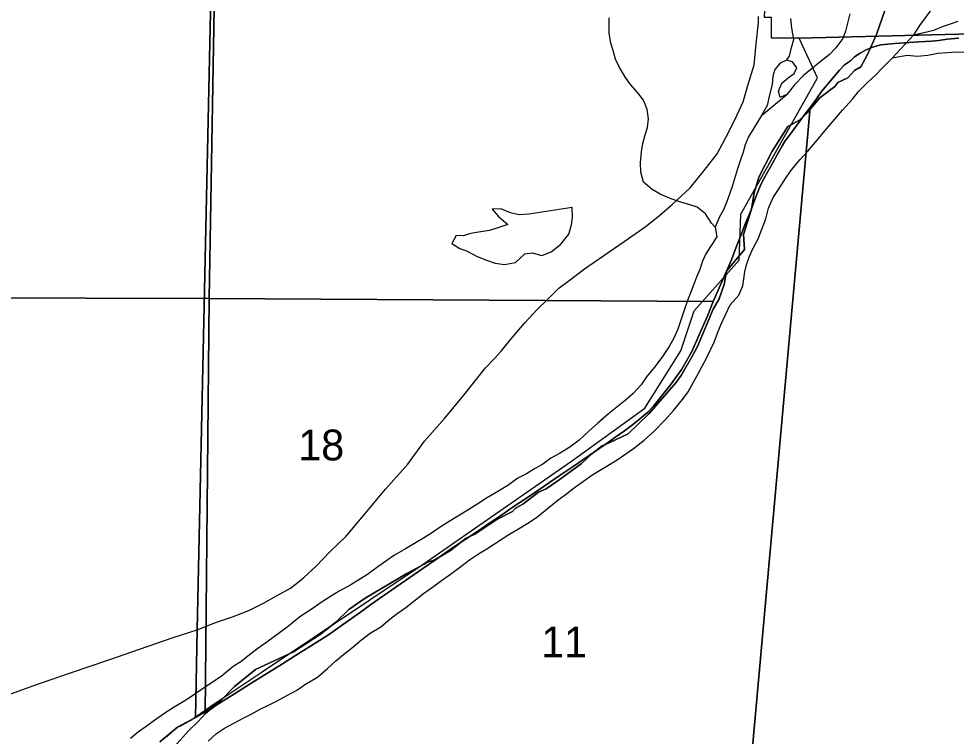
# Model space of a CAD drawing. Extents: x 1310247 to 1552180, y 377264 to 706493.
# Drawn here: x 1376326 to 1383052, y 499946 to 505092 of the extents above; entities that cross this region are included whole.
import ezdxf

# ---------------------------------------------------------------- set-up
doc = ezdxf.new("R2010")
doc.units = 0
for name, color, linetype in [('GM_X_Corporation', 7, 'Continuous'), ('GM_X_Major_River', 7, 'Continuous'), ('GM_X_Minor_Lake', 7, 'Continuous'), ('GM_X_Minor_River', 7, 'Continuous'), ('GM_X_Section', 7, 'Continuous'), ('GM_X_Section_Text', 7, 'Continuous'), ('GM_X_State_Route', 7, 'Continuous'), ('GM_X_Township', 7, 'Continuous')]:
    doc.layers.add(name, color=color, linetype=linetype)

msp = doc.modelspace()

# ---------------------------------------------------------------- linework, layer by layer
at = {"layer": 'GM_X_Corporation'}
for points in [[(1383353.6, 504989.2), (1381925.6, 504951.4), (1381725.6, 504951.4), (1381725.6, 505100.1), (1381677.1, 505100.2), (1381698.4, 505559.8), (1381687.8, 506000.9), (1381661.3, 506197.5), (1381703.8, 506404.7), (1381746.4, 506856.4), (1381788.9, 507223), (1383271.5, 507225.7)], [(1377389.1, 499942.2), (1377435.9, 499986.6), (1377464.5, 500010.5), (1377489.6, 500021.6), (1377522.2, 500040.5), (1377561.1, 500061.7), (1377728.2, 500177.6), (1378073.2, 500407.8), (1379228.1, 501181.2), (1380292.8, 501917.7), (1380817.6, 502298.2), (1381075.9, 502710.6), (1381171.9, 502996.2), (1381495.1, 503360.3), (1381505.7, 503689.7), (1382056.7, 504667), (1381925.6, 504951.4), (1383353.6, 504989.2)]]:
    msp.add_lwpolyline(points, dxfattribs=at)
at = {"layer": 'GM_X_Major_River'}
for p, q in [((1382591.4, 504808.4), (1382748.5, 504977)), ((1381654.9, 504397.6), (1381835.6, 504547.5))]:
    msp.add_line(p, q, dxfattribs=at)
for points in [[(1382748.5, 504977), (1382790.5, 505042.2), (1382838.4, 505107.2), (1382884.3, 505170.2), (1382917.9, 505223.6), (1382949.5, 505279), (1382985.2, 505336.3), (1383025.3, 505407.6), (1383069.4, 505480.7)], [(1382289.1, 505128), (1382257.5, 505002.2), (1382238.1, 504950.5), (1382188, 504883.6), (1382140.5, 504832.6), (1382072.8, 504780.2), (1382009.2, 504727.6), (1381955.8, 504684.9), (1381891.8, 504618.3), (1381835.6, 504547.5)], [(1377684.2, 499911.5), (1377745.9, 499966.1), (1377803.2, 500004.7), (1377868.4, 500039.1), (1377941.7, 500077.3), (1377998.6, 500105.9), (1378053.7, 500138.6), (1378122.8, 500170.9), (1378179.8, 500199.5), (1378253.2, 500241.7), (1378326.5, 500277.9), (1378379.7, 500316.7), (1378469.5, 500370.5), (1378541.4, 500430.8), (1378601.2, 500487.5), (1378666.9, 500542), (1378722.2, 500584.7), (1378775.6, 500629.5), (1378847.4, 500685.8), (1378922.9, 500730), (1378988.7, 500786.5), (1379042, 500827.2), (1379103.4, 500869.8), (1379160.8, 500914.5), (1379230.6, 500970.8), (1379294, 501015.3), (1379349.3, 501056), (1379423, 501108.3), (1379496.7, 501162.6), (1379560.3, 501211.1), (1379623.7, 501253.6), (1379684.9, 501290.1), (1379740.1, 501326.8), (1379842.2, 501392.4), (1379911.6, 501432.7), (1379978.9, 501473.1), (1380040.3, 501515.6), (1380118.2, 501577.8), (1380194.2, 501638), (1380245.4, 501676.8), (1380313.1, 501729.3), (1380376.6, 501775.8), (1380429.8, 501814.5), (1380480.8, 501845.3), (1380540, 501879.9), (1380619.6, 501928), (1380674.8, 501966.7), (1380736.2, 502009.2), (1380814.1, 502069.4), (1380884.1, 502133.8), (1380962.6, 502216.1), (1381022.7, 502282.8), (1381087, 502361.4), (1381128.7, 502416.6), (1381168.9, 502489.8), (1381202.6, 502549.2), (1381230.1, 502600.7), (1381259.8, 502658.2), (1381289.5, 502717.6), (1381315.1, 502771.2), (1381339, 502836.9), (1381362.7, 502896.5), (1381394.6, 502964), (1381428.8, 503039.4), (1381491, 503110.1), (1381520.9, 503175.6), (1381535.7, 503275.6), (1381547.1, 503327.6), (1381568.9, 503389.2), (1381594.6, 503446.8), (1381630.5, 503514.2), (1381667.2, 503605.6), (1381684.7, 503657.4), (1381704.8, 503733.2), (1381739.1, 503810.6), (1381780.9, 503873.8), (1381827.1, 503946.9), (1381870.9, 504008), (1381933.2, 504082.7), (1381987, 504141.5), (1382053.4, 504220.1), (1382109.5, 504288.9), (1382167.5, 504355.7), (1382235.9, 504436.2), (1382308.3, 504514.6), (1382350, 504569.8), (1382416, 504634.3), (1382471.6, 504687.1), (1382521.2, 504738), (1382591.4, 504808.4)], [(1381835.6, 504547.5), (1381788.9, 504526.6), (1381776.1, 504571.2), (1381799.7, 504628.8), (1381849, 504669.7), (1381887.9, 504698.8), (1381909.2, 504740.4), (1381878.2, 504783.4), (1381834.4, 504794.6), (1381789.7, 504773.7), (1381750.2, 504726.6), (1381736.9, 504680.7)], [(1381736.9, 504680.7), (1381731.3, 504620.6), (1381713.2, 504546.7), (1381695, 504468.9), (1381654.9, 504397.6)], [(1381654.9, 504397.6), (1381560.4, 504245.4), (1381536.7, 504187.8), (1381523.2, 504133.9), (1381501.4, 504072.2), (1381481.8, 504014.5), (1381446.4, 503894.9), (1381426.8, 503841.2), (1381402.9, 503773.5), (1381381.4, 503721.8), (1381353.9, 503670.3), (1381321.8, 503596.8), (1381333.9, 503528.2), (1381289.9, 503459.1), (1381254.3, 503405.8), (1381230.8, 503354.2), (1381211.1, 503294.4), (1381189.5, 503238.7), (1381167.8, 503181.1), (1381144.2, 503125.4), (1381120.4, 503063.8), (1381096.4, 502994.1), (1381078.8, 502936.3), (1381054.8, 502864.6), (1381026.9, 502801.1), (1380991.2, 502741.8), (1380938.8, 502662.8), (1380886.7, 502593.9), (1380830.6, 502523.1), (1380790.9, 502465.9), (1380735.1, 502405.1), (1380677.5, 502354.4), (1380615.9, 502305.8), (1380556.4, 502259.2), (1380480.3, 502190.9), (1380418.6, 502136.3), (1380346.5, 502070), (1380278.9, 502019.5), (1380205.4, 501973.3), (1380142.3, 501940.8), (1380084.9, 501896.2), (1380025.8, 501863.6), (1379968.6, 501829), (1379907.5, 501796.5), (1379835.9, 501744.2), (1379739.9, 501686.5), (1379680.8, 501653.9), (1379619.5, 501613.4), (1379556.2, 501572.9), (1379501.1, 501538.2), (1379413.3, 501486.3), (1379356.1, 501449.7), (1379300.9, 501413), (1379229.4, 501366.7), (1379176.4, 501336), (1379100.9, 501289.8), (1379021.3, 501243.7), (1378966.1, 501207), (1378902.7, 501160.5), (1378828.9, 501106.2), (1378777.9, 501075.5), (1378708.4, 501031.1), (1378625, 500987.2), (1378561.7, 500948.7), (1378510.6, 500915.9), (1378424.7, 500856), (1378342.9, 500801.9), (1378260.8, 500735.8), (1378187, 500679.5), (1378115.3, 500627.2), (1378041.7, 500574.9), (1377982.2, 500530.3), (1377920.6, 500479.8), (1377865.5, 500445.1), (1377779.3, 500375.1), (1377701.6, 500324.9), (1377628, 500274.7), (1377566.6, 500232.1), (1377505.4, 500193.6), (1377440.1, 500155.2), (1377374.7, 500112.7), (1377303, 500060.4), (1377239.6, 500015.9), (1377186.3, 499977.1), (1377126.9, 499930.5)]]:
    msp.add_lwpolyline(points, dxfattribs=at)
at = {"layer": 'GM_X_Minor_Lake'}
for points in [[(1379985.8, 503689.1), (1379917.4, 503684.9), (1379853.6, 503698.7), (1379784.2, 503728.7), (1379721.9, 503726.4), (1379768.6, 503672.9), (1379835.3, 503616.8), (1379770.4, 503594.5), (1379703.7, 503574.2), (1379625, 503560.2), (1379570.6, 503551.6), (1379513.9, 503535.1), (1379463.8, 503536.4), (1379432.2, 503481), (1379491.3, 503443.3), (1379543, 503423.8), (1379610.3, 503389.8), (1379673.7, 503362), (1379743.4, 503340), (1379811.3, 503330.1), (1379890, 503344.1), (1379957.9, 503404.6), (1380008.3, 503413.2), (1380078, 503393.3), (1380144.9, 503419.6), (1380214.7, 503476), (1380272.8, 503546.8), (1380290.8, 503614.6), (1380298.3, 503668.6), (1380296.2, 503739)], [(1380296.2, 503739), (1379985.8, 503689.1)]]:
    msp.add_lwpolyline(points, dxfattribs=at)
at = {"layer": 'GM_X_Minor_River'}
msp.add_line((1382748.5, 504977), (1382591.4, 504808.4), dxfattribs=at)
for points in [[(1381321.8, 503596.8), (1381296.5, 503625.7), (1381252.2, 503693.1), (1381193.3, 503741), (1381125.7, 503762.9), (1381065.9, 503778.5), (1380994.4, 503804.6), (1380928.9, 503832.5), (1380869.6, 503866.2), (1380808.9, 503920.1), (1380788.8, 503991), (1380786.6, 504059.3), (1380792.8, 504137.5), (1380802.5, 504197.5), (1380820.3, 504259.4), (1380837.7, 504311.1), (1380843.5, 504373.3), (1380833.3, 504441.8), (1380807.1, 504508.9), (1380768.3, 504560.1), (1380713.8, 504619.9), (1380679.1, 504671), (1380634.9, 504742.6), (1380608.4, 504801.5), (1380590.1, 504864.3), (1380573.5, 504917), (1380561.4, 504987.7), (1380560.8, 505039.9), (1380562.4, 505098.1)], [(1381834.4, 504794.6), (1381855.3, 504824.2), (1381871, 504886.1), (1381886.7, 504943.9), (1381872.8, 505024.7), (1381864.7, 505093.2)], [(1382748.5, 504977), (1382891.9, 505009.3), (1382960.9, 505037.6), (1383011.6, 505056.3), (1383066.3, 505074.9)], [(1383108.3, 504850.8), (1383046.1, 504852.4), (1382989.8, 504847.9), (1382919.4, 504841.8), (1382846.8, 504827.7), (1382770.3, 504821.7), (1382700.3, 504827.6), (1382591.4, 504808.4)]]:
    msp.add_lwpolyline(points, dxfattribs=at)
at = {"layer": 'GM_X_Section'}
for points in [[(1372445.8, 508439.6), (1377782.5, 508365.7), (1377691.2, 503085.5), (1372373.2, 503099.2)], [(1377691.2, 503085.5), (1381309, 503064.7), (1381268.7, 502965.6), (1381154.8, 502706.2), (1381083.8, 502577.8), (1381001.2, 502465.7), (1380879.8, 502314.4), (1380838.8, 502271.4), (1380795.9, 502234.4), (1380763.2, 502205.1), (1380718.5, 502172.1), (1380671.6, 502135.2), (1380610.7, 502092.6), (1380539.5, 502042.2), (1380456.2, 501986.1), (1380303.8, 501881.6), (1380204.3, 501813.9), (1380094.6, 501740.4), (1379976.7, 501659.1), (1379867.1, 501587.6), (1379781.7, 501527.5), (1379698.4, 501471.4), (1379619.1, 501417.2), (1379527.8, 501357.3), (1379438.4, 501297.3), (1379316.5, 501212.1), (1379225, 501148.2), (1378968.9, 500972.1), (1378859.2, 500894.6), (1378777.8, 500836.4), (1378647.7, 500745.4), (1378548.1, 500673.7), (1378446.5, 500608), (1378312.7, 500525.1), (1378217.3, 500465.2), (1378117.8, 500403.5), (1377986, 500322.5), (1377874.3, 500249.1), (1377793.2, 500200.9), (1377740.4, 500166.1), (1377697.7, 500135.1), (1377663, 500105.9)]]:
    msp.add_lwpolyline(points, close=True, dxfattribs=at)
for points in [[(1383070.3, 504952.5), (1382986.1, 504944.4), (1382927.9, 504935.7), (1382873.8, 504931), (1382829.7, 504928), (1382783.7, 504925), (1382611.4, 504913), (1382511.2, 504905.3), (1382450.8, 504888.7), (1382404.3, 504867.7), (1382361.8, 504844.7), (1382321.2, 504819.6), (1382292.6, 504790.3), (1382249.9, 504761.2), (1382215, 504722), (1382085.5, 504569), (1382048.3, 504517.8), (1382002.8, 504454.9), (1381959.6, 504399.9), (1381858.4, 504260.2), (1381823.4, 504217), (1381800.4, 504175.5), (1381769.2, 504120.2), (1381740, 504068.9), (1381698.2, 503991.8), (1381671.1, 503944.4), (1381652.3, 503906.9), (1381633.3, 503863.3), (1381605.7, 503795.9), (1381580.1, 503722.5), (1381535.5, 503613.5), (1381510, 503548.1), (1381473.9, 503452.9), (1381439.8, 503361.7), (1381404, 503282.5), (1381309, 503064.7), (1377691.2, 503085.5), (1377782.5, 508365.7)], [(1381559.9, 499522.7), (1382002.8, 504454.9), (1382048.3, 504517.8), (1382085.5, 504569), (1382215, 504722), (1382249.9, 504761.2), (1382292.6, 504790.3), (1382321.2, 504819.6), (1382361.8, 504844.7), (1382404.3, 504867.7), (1382450.8, 504888.7), (1382511.2, 504905.3), (1382611.4, 504913), (1382783.7, 504925), (1382829.7, 504928), (1382873.8, 504931), (1382927.9, 504935.7), (1382986.1, 504944.4), (1383070.3, 504952.5)], [(1377441.6, 499870.9), (1377544.2, 499984.6), (1377613.8, 500053), (1377663, 500105.9), (1377697.7, 500135.1), (1377740.4, 500166.1), (1377793.2, 500200.9), (1377874.3, 500249.1), (1377986, 500322.5), (1378117.8, 500403.5), (1378217.3, 500465.2), (1378312.7, 500525.1), (1378446.5, 500608), (1378548.1, 500673.7), (1378647.7, 500745.4), (1378777.8, 500836.4), (1378859.2, 500894.6), (1378968.9, 500972.1), (1379225, 501148.2), (1379316.5, 501212.1), (1379438.4, 501297.3), (1379527.8, 501357.3), (1379619.1, 501417.2), (1379698.4, 501471.4), (1379781.7, 501527.5), (1379867.1, 501587.6), (1379976.7, 501659.1), (1380094.6, 501740.4), (1380204.3, 501813.9), (1380303.8, 501881.6), (1380456.2, 501986.1), (1380539.5, 502042.2), (1380610.7, 502092.6), (1380671.6, 502135.2), (1380718.5, 502172.1), (1380763.2, 502205.1), (1380795.9, 502234.4), (1380838.8, 502271.4), (1380879.8, 502314.4), (1381001.2, 502465.7), (1381083.8, 502577.8), (1381154.8, 502706.2), (1381268.7, 502965.6), (1381309, 503064.7), (1381404, 503282.5), (1381439.8, 503361.7), (1381473.9, 503452.9), (1381510, 503548.1), (1381535.5, 503613.5), (1381580.1, 503722.5), (1381605.7, 503795.9), (1381633.3, 503863.3), (1381652.3, 503906.9), (1381671.1, 503944.4), (1381698.2, 503991.8), (1381740, 504068.9), (1381769.2, 504120.2), (1381800.4, 504175.5), (1381823.4, 504217), (1381858.4, 504260.2), (1381959.6, 504399.9), (1382002.8, 504454.9), (1381559.9, 499522.7)], [(1372373.3, 499782.9), (1372373.2, 503099.2), (1377691.2, 503085.5), (1377663, 500105.9), (1377613.8, 500053), (1377544.2, 499984.6), (1377441.6, 499870.9)]]:
    msp.add_lwpolyline(points, dxfattribs=at)
at = {"layer": 'GM_X_State_Route'}
for points in [[(1379743.3, 502660.6), (1379786.5, 502707.5), (1379871.5, 502810.1), (1379956.4, 502910.4), (1380043.7, 503003.6), (1380123.9, 503083.8), (1380199.7, 503159.8), (1380274.8, 503214.7), (1380385.8, 503298.5), (1380523.7, 503394), (1380670, 503493.1), (1380821, 503600.4), (1380923.6, 503681.8), (1381015.6, 503762), (1381143, 503880), (1381244.4, 504002.6), (1381335.6, 504123.3), (1381397.7, 504240.6), (1381466.2, 504371.8), (1381523, 504497), (1381557.7, 504613.2), (1381601, 504762.3), (1381616.7, 504911.4), (1381634, 505064), (1381634.3, 505108.4)], [(1376242.1, 500240), (1376435.6, 500309.6), (1376690.3, 500398), (1376980.5, 500497.1), (1377191.6, 500570.3), (1377433.4, 500654), (1377605.7, 500708.3), (1377744.8, 500764.9), (1377860.4, 500802.6), (1377977.2, 500848.6), (1378082.2, 500899.3), (1378175.3, 500952.4), (1378276.7, 501008.3), (1378343.1, 501061.6), (1378372.2, 501084.9), (1378459.6, 501165.7), (1378557.5, 501268.3), (1378674.3, 501381.8), (1378802.9, 501531.5), (1378957.3, 501717.9), (1379117.2, 501897.6), (1379236.9, 502062.3), (1379381.2, 502225), (1379520, 502391.4), (1379675.7, 502587.2), (1379743.3, 502660.6)]]:
    msp.add_lwpolyline(points, dxfattribs=at)
at = {"layer": 'GM_X_Township'}
for points in [[(1364164.5, 513845.1), (1368014.4, 513825.3), (1368609.6, 513814.9), (1369066.7, 513817.2), (1369488, 513814.9), (1370392.5, 513802.6), (1371848.8, 513777.9), (1372591.9, 513770.6), (1373324, 513763.4), (1375822.3, 513738.9), (1377854.8, 513715.5), (1377805.2, 510595.3), (1377766.1, 508131), (1377605.8, 500708.3), (1377593.7, 500080.7), (1377464.5, 500010.5), (1377338.3, 499907)], [(1382560.9, 505212.7), (1382478.6, 504979), (1382415.9, 504835.6), (1382366.6, 504747.6), (1382322.9, 504720.1), (1382274.1, 504669.1), (1382203.1, 504634.1), (1382181.1, 504605.8), (1382073.1, 504525.2), (1381982.1, 504417.3), (1381926.8, 504364.7), (1381842.7, 504318.6), (1381729, 504137.6), (1381635, 503956), (1381601.4, 503844), (1381582.9, 503726.6), (1381524.4, 503545.6), (1381532.5, 503435.7), (1381403.8, 503282.6), (1381387.8, 503186.1), (1381350.5, 503083.2), (1381307.8, 503008.3), (1381195.4, 502740.9), (1381152.4, 502663), (1381079, 502533.4), (1381040.2, 502479.9), (1380847.6, 502258.1), (1380698.2, 502114.4), (1380567.8, 502053.7), (1380512.6, 502028.1), (1380436.8, 501972.4), (1380360.6, 501900.4), (1380186.3, 501772.1), (1380108.9, 501719.3), (1380055.9, 501695.6), (1379943.1, 501611.4), (1379890.1, 501582.3), (1379867.3, 501559), (1379756.3, 501499.4), (1379597.4, 501395.3), (1379535.7, 501365.6), (1379423.5, 501279.3), (1379306.5, 501209.9), (1379265.8, 501195.8), (1379110.6, 501114.1), (1378811.5, 500935.3), (1378695.1, 500855), (1378600.7, 500763.9), (1378488, 500676.2), (1378297, 500551.1), (1378025.2, 500424.8), (1377873.6, 500302.2), (1377773.2, 500200.4), (1377700.3, 500142.9), (1377593.7, 500080.7), (1377605.8, 500708.3), (1377766.1, 508131)], [(1377338.3, 499907), (1377464.5, 500010.5), (1377593.7, 500080.7), (1377700.3, 500142.9), (1377773.2, 500200.4), (1377873.6, 500302.2), (1378025.2, 500424.8), (1378297, 500551.1), (1378488, 500676.2), (1378600.7, 500763.9), (1378695.1, 500855), (1378811.5, 500935.3), (1379110.6, 501114.1), (1379265.8, 501195.8), (1379306.5, 501209.9), (1379423.5, 501279.3), (1379535.7, 501365.6), (1379597.4, 501395.3), (1379756.3, 501499.4), (1379867.3, 501559), (1379890.1, 501582.3), (1379943.1, 501611.4), (1380055.9, 501695.6), (1380108.9, 501719.3), (1380186.3, 501772.1), (1380360.6, 501900.4), (1380436.8, 501972.4), (1380512.6, 502028.1), (1380567.8, 502053.7), (1380698.2, 502114.4), (1380847.6, 502258.1), (1381040.2, 502479.9), (1381079, 502533.4), (1381152.4, 502663), (1381195.4, 502740.9), (1381307.8, 503008.3), (1381350.5, 503083.2), (1381387.8, 503186.1), (1381403.8, 503282.6), (1381532.5, 503435.7), (1381524.4, 503545.6), (1381582.9, 503726.6), (1381601.4, 503844), (1381635, 503956), (1381729, 504137.6), (1381842.7, 504318.6), (1381926.8, 504364.7), (1381982.1, 504417.3), (1382073.1, 504525.2), (1382181.1, 504605.8), (1382203.1, 504634.1), (1382274.1, 504669.1), (1382322.9, 504720.1), (1382366.6, 504747.6), (1382415.9, 504835.6), (1382478.6, 504979), (1382560.9, 505212.7)]]:
    msp.add_lwpolyline(points, dxfattribs=at)

# ---------------------------------------------------------------- texts
at = {"layer": 'GM_X_Section_Text'}
for s, p in [('18', (1378332, 501924.4)), ('11', (1380074.4, 500512))]:
    msp.add_text(s, height=221, rotation=0.00001, dxfattribs=at).set_placement(p)

doc.saveas('drawing.dxf')
